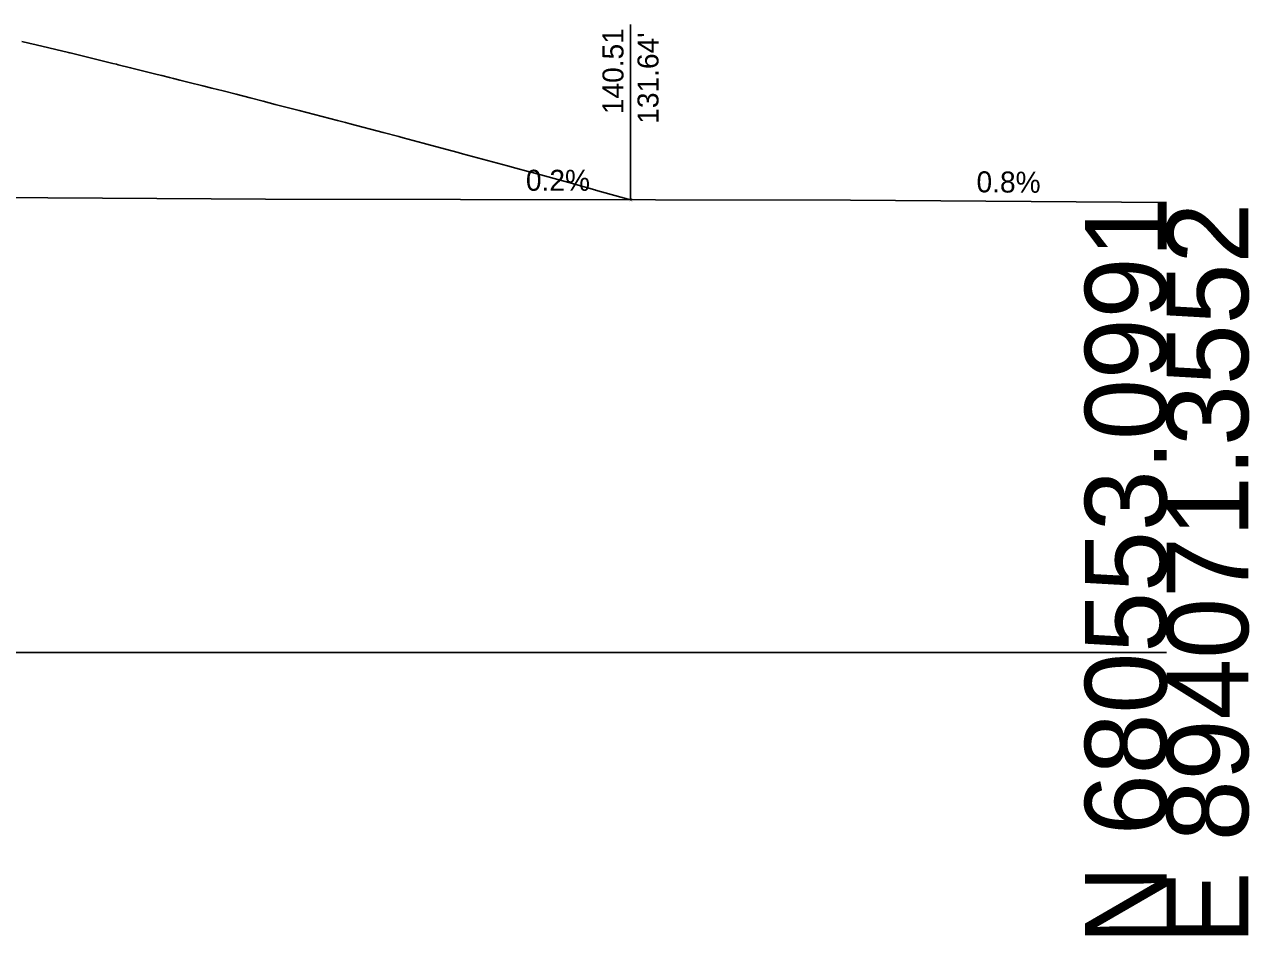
# Model space of a CAD drawing. Extents: x -26 to 4403, y -13 to 9578.
# Drawn here: x 1360.88 to 1402.84, y 7990.31 to 8021.51 of the extents above; entities that cross this region are included whole.
import ezdxf

# ---------------------------------------------------------------- set-up
doc = ezdxf.new("R2010")
doc.units = 0
for name, color, linetype in [('DTM_X_GROUND', 7, 'Continuous'), ('X_PROFILES_1', 7, 'Continuous'), ('XS_CELL', 7, 'Continuous'), ('XS_P_GROUND', 7, 'Continuous'), ('XS_P_TX_CLEARZONE', 7, 'Continuous'), ('XS_P_TX_FS_BS', 7, 'Continuous')]:
    doc.layers.add(name, color=color, linetype=linetype)

msp = doc.modelspace()

# ---------------------------------------------------------------- linework, layer by layer
at = {"layer": 'DTM_X_GROUND'}
msp.add_lwpolyline([(1305.181, 8015.791), (1306.376, 8015.793), (1308.059, 8015.796), (1331.863, 8015.749), (1369.14, 8015.527), (1389.173, 8015.495), (1400, 8015.407)], dxfattribs=at)
at = {"layer": 'XS_CELL'}
msp.add_line((1250, 8000), (1400, 8000), dxfattribs=at)
at = {"layer": 'XS_P_GROUND'}
msp.add_lwpolyline([(1360.794, 8020.926), (1361.029, 8020.871), (1361.275, 8020.813), (1362.387, 8020.544), (1362.432, 8020.534), (1362.446, 8020.531), (1362.809, 8020.443), (1363.91, 8020.172), (1364.033, 8020.143), (1364.086, 8020.13), (1364.516, 8020.025), (1365.422, 8019.799), (1365.581, 8019.76), (1365.852, 8019.693), (1365.985, 8019.66), (1366.197, 8019.606), (1366.519, 8019.526), (1366.986, 8019.407), (1367.297, 8019.33), (1367.69, 8019.23), (1368.125, 8019.12), (1368.607, 8018.996), (1369.05, 8018.882), (1369.47, 8018.772), (1369.919, 8018.658), (1370.287, 8018.564), (1371.072, 8018.36), (1371.605, 8018.22), (1371.874, 8018.15), (1372.033, 8018.109), (1373.162, 8017.811), (1373.697, 8017.668), (1373.741, 8017.657), (1373.848, 8017.629), (1374.534, 8017.446), (1374.782, 8017.378), (1375.52, 8017.18), (1375.737, 8017.12), (1375.77, 8017.112), (1375.888, 8017.081), (1377.424, 8016.665), (1377.708, 8016.587), (1378.128, 8016.474), (1378.19, 8016.457), (1379.651, 8016.056), (1379.765, 8016.025), (1380.41, 8015.846), (1380.44, 8015.837), (1381.637, 8015.507)], dxfattribs=at)
at = {"layer": 'XS_P_TX_CLEARZONE'}
msp.add_line((1381.637, 8015.507), (1381.637, 8021.507), dxfattribs=at)

# ---------------------------------------------------------------- texts
at = {"layer": 'X_PROFILES_1'}
msp.add_text('X', height=0.12, dxfattribs=at).set_placement((1381.598, 8015.447))
at = {"layer": 'XS_CELL'}
for s, p in [('N 680553.0991', (1400, 7990)), ('E 894071.3552', (1402.8, 7990))]:
    msp.add_text(s, height=2.8, rotation=90, dxfattribs=at).set_placement(p)
at = {"layer": 'XS_P_TX_CLEARZONE'}
for s, p in [('140.51', (1381.397, 8018.436)), ("131.64'", (1382.597, 8018.107))]:
    msp.add_text(s, height=0.72, rotation=90, dxfattribs=at).set_placement(p)
at = {"layer": 'XS_P_TX_FS_BS'}
for s, rotation, p in [('0.2%', 359.9087, (1378.055, 8015.813)), ('0.2%', 359.9087, (1378.055, 8015.813)), ('0.8%', 359.5348, (1393.487, 8015.76)), ('0.8%', 359.5348, (1393.487, 8015.76))]:
    msp.add_text(s, height=0.72, rotation=rotation, dxfattribs=at).set_placement(p)

doc.saveas('drawing.dxf')
